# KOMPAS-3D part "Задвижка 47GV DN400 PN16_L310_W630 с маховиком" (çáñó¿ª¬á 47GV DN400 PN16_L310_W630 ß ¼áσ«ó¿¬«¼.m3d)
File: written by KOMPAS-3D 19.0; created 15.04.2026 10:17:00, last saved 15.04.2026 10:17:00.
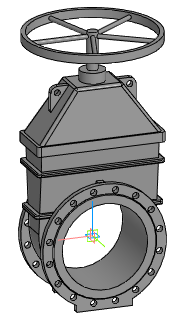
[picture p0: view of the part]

Document properties: Автор: Евгений; Полное имя файла: Z:\3.Личные\kachalov\3d для проектировщиков\2.1 Тип 47GV, 47GV.Z\Задвижка 47GV_DN40-DN600\stp_Задвижка 47GV\Задвижка 47GV DN400 PN16_L310_W630 с маховиком.m3d

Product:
- Part/product: Задвижка 47GV DN400 PN16_L310_W630 с маховиком

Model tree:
1. Операция без истории:1  (labels: Задвижка 47GV DN400 PN16_L310_W630 с маховиком)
